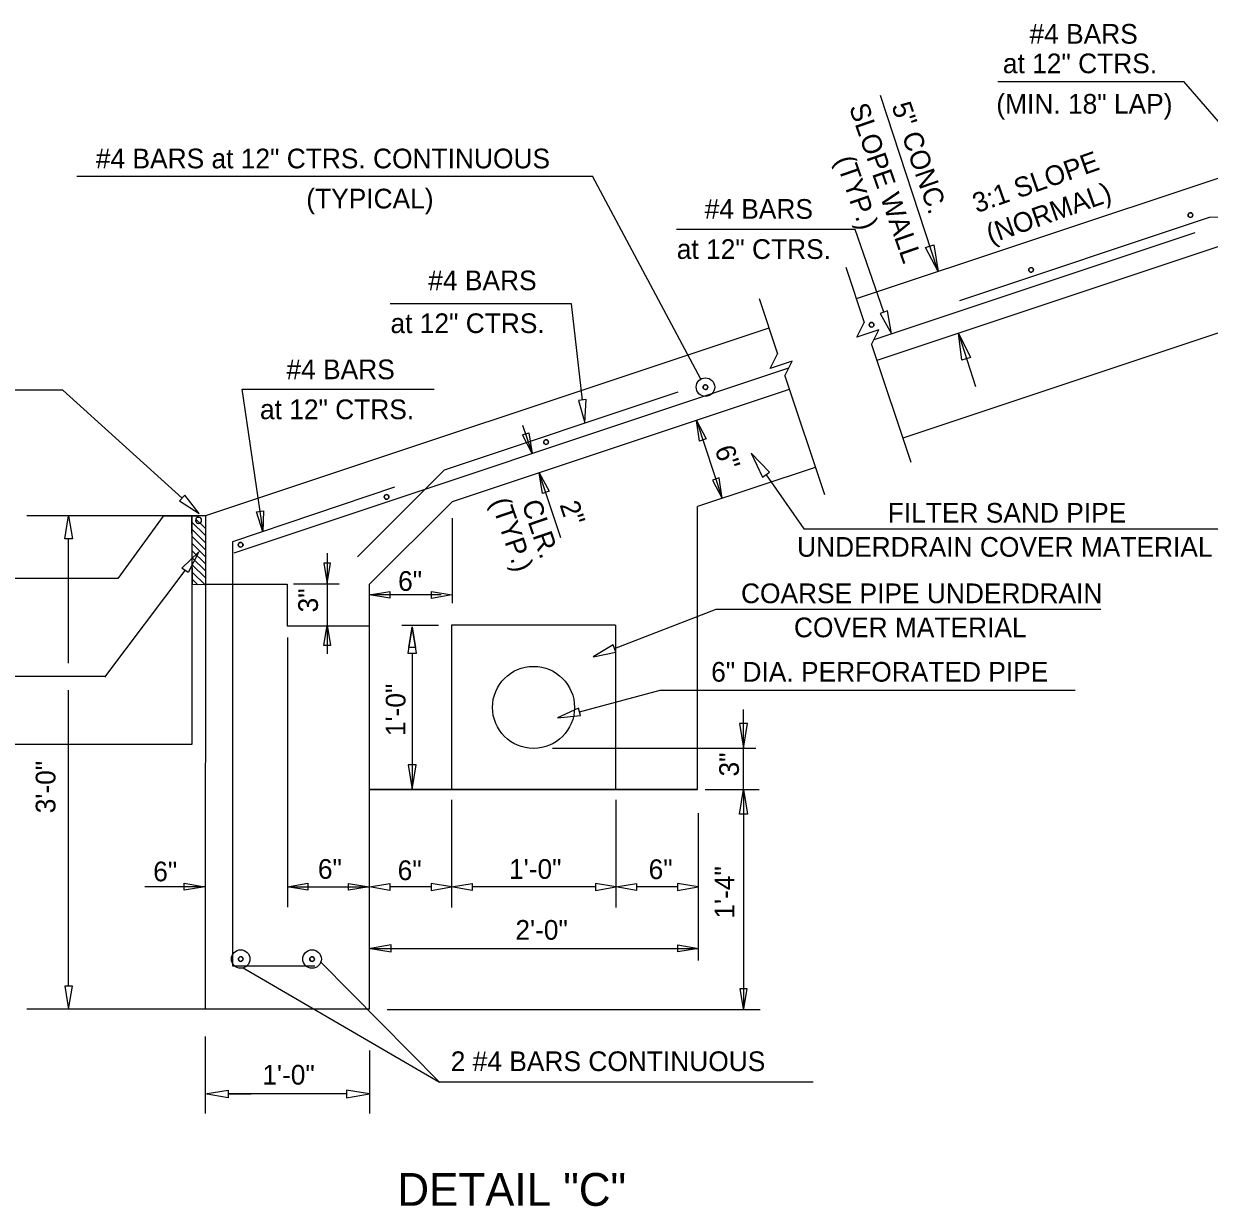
# Model space of a CAD drawing. Extents: x 570 to 2152770, y 726 to 139926.
# Drawn here: x 2152518.59 to 2152525.81, y 139385.58 to 139392.78 of the extents above; entities that cross this region are included whole.
import ezdxf

# ---------------------------------------------------------------- set-up
doc = ezdxf.new("R2010")
doc.units = 0
for name, color, linetype in [('4', 7, 'Continuous'), ('5', 7, 'Continuous'), ('6', 7, 'Continuous'), ('7', 7, 'Continuous'), ('9', 7, 'Continuous'), ('Default', 7, 'Continuous'), ('PR_Dimensions', 7, 'Continuous'), ('PR_Reinforcing', 7, 'Continuous'), ('PR_SlopeWall', 7, 'Continuous'), ('T', 7, 'Continuous'), ('T-Title', 7, 'Continuous'), ('TOPO_Concrete', 7, 'Continuous'), ('WEEPHOLES', 7, 'Continuous')]:
    doc.layers.add(name, color=color, linetype=linetype)

# ---------------------------------------------------------------- blocks, each defined once
blk = doc.blocks.new('DWG01008_7')
at = {"layer": 'Default'}
for p, q in [((-0.0132, 0), (0, 0.0132)), ((0, 0.0132), (0, -0.0132)), ((0, -0.0132), (0.0132, 0))]:
    blk.add_line(p, q, dxfattribs=at)
blk = doc.blocks.new('ARROWHD_15')
at = {"layer": 'Default'}
blk.add_lwpolyline([(0.0261, -0.0045), (0.0261, 0.0043), (-0.0004, -0.0001)], close=True, dxfattribs=at)

msp = doc.modelspace()

# ---------------------------------------------------------------- linework, layer by layer
at = {"layer": '4'}
for p, q in [((2152519.614, 139389.3656), (2152519.6114, 139389.7831)), ((2152519.6925, 139389.3691), (2152520.1925, 139389.3691)), ((2152520.1925, 139389.3691), (2152520.1925, 139389.1168)), ((2152520.1925, 139389.1168), (2152520.6925, 139389.1168))]:
    msp.add_line(p, q, dxfattribs=at)
at = {"layer": '5'}
for p, q in [((2152519.6917, 139389.7858), (2152519.6114, 139389.7831)), ((2152519.694, 139389.3684), (2152519.6137, 139389.3657))]:
    msp.add_line(p, q, dxfattribs=at)
at = {"layer": '6'}
msp.add_line((2152518.8249, 139390.5527), (2152515.2246, 139390.5527), dxfattribs=at)
at = {"layer": '7'}
for p, q in [((2152525.9667, 139390.9334), (2152523.9433, 139390.2589)), ((2152523.4102, 139390.0812), (2152522.693, 139389.8421)), ((2152522.693, 139388.1191), (2152522.693, 139389.8421)), ((2152522.693, 139388.1191), (2152520.693, 139388.1191))]:
    msp.add_line(p, q, dxfattribs=at)
at = {"layer": '9'}
for start, end in [(20.3306, 200.3306), (200.3306, 20.3306)]:
    msp.add_arc((2152523.7534, 139390.9506), 0.0143, start, end, dxfattribs=at)
at = {"layer": 'Default'}
for p, q in [((2152519.6919, 139389.6675), (2152519.6116, 139389.7468)), ((2152519.6916, 139389.7107), (2152519.6348, 139389.7668)), ((2152519.6922, 139389.6242), (2152519.6119, 139389.7035)), ((2152519.6924, 139389.5809), (2152519.6121, 139389.6602)), ((2152519.6927, 139389.5376), (2152519.6124, 139389.6169)), ((2152519.693, 139389.4943), (2152519.6127, 139389.5736)), ((2152519.6932, 139389.451), (2152519.6129, 139389.5303)), ((2152519.6935, 139389.4077), (2152519.6132, 139389.487)), ((2152519.6938, 139389.3645), (2152519.6135, 139389.4438)), ((2152519.6479, 139389.3667), (2152519.6137, 139389.4005))]:
    msp.add_line(p, q, dxfattribs=at)
at = {"layer": 'Defpoints'}
for p, q in [((2152519.6927, 139389.7858), (2152518.605, 139389.7858)), ((2152519.6927, 139386.7808), (2152518.605, 139386.7808))]:
    msp.add_line(p, q, dxfattribs=at)
at = {"layer": 'PR_Dimensions'}
for p, q in [((2152524.5223, 139392.4329), (2152525.6553, 139392.4329)), ((2152524.1583, 139391.2743), (2152523.8084, 139392.3468)), ((2152518.9105, 139391.8554), (2152522.0517, 139391.8554)), ((2152523.6523, 139391.5309), (2152522.5643, 139391.5309)), ((2152523.5961, 139391.3006), (2152523.7082, 139390.9643)), ((2152523.0673, 139391.1099), (2152523.1794, 139390.7736)), ((2152521.9237, 139391.0789), (2152520.8196, 139391.0789)), ((2152524.3895, 139390.5722), (2152524.286, 139390.8895)), ((2152523.7529, 139390.8302), (2152523.9916, 139390.1139)), ((2152523.2241, 139390.6395), (2152523.4655, 139389.9152)), ((2152520.0446, 139389.6891), (2152519.9167, 139390.5572)), ((2152519.9167, 139390.5572), (2152521.0867, 139390.5572)), ((2152521.6777, 139390.1885), (2152521.6282, 139390.3365)), ((2152522.6853, 139390.3666), (2152522.8436, 139389.8915)), ((2152521.8599, 139389.652), (2152521.7277, 139390.0474)), ((2152519.653, 139389.7858), (2152518.7392, 139389.7858)), ((2152521.1969, 139389.7722), (2152521.1969, 139389.2532)), ((2152518.8592, 139388.8881), (2152518.8592, 139389.6458)), ((2152520.4354, 139389.5592), (2152520.4354, 139389.1207)), ((2152520.5086, 139389.3697), (2152520.2294, 139389.3697)), ((2152521.1312, 139389.3044), (2152520.696, 139389.3044)), ((2152522.8053, 139389.2168), (2152525.1502, 139389.2168)), ((2152520.4354, 139389.1207), (2152520.4354, 139388.9459)), ((2152520.8895, 139389.1207), (2152521.1142, 139389.1207)), ((2152520.193, 139389.0439), (2152520.193, 139387.401)), ((2152516.2177, 139388.8086), (2152519.0795, 139388.8086)), ((2152518.8592, 139386.9208), (2152518.8592, 139388.7234)), ((2152522.4641, 139388.7248), (2152524.993, 139388.7248)), ((2152522.9726, 139388.1191), (2152522.9726, 139388.6058)), ((2152521.8092, 139388.3695), (2152523.0485, 139388.3695)), ((2152520.693, 139388.1191), (2152522.693, 139388.1191)), ((2152522.7399, 139388.1191), (2152523.0677, 139388.1191)), ((2152522.7432, 139388.1191), (2152523.0212, 139388.1191)), ((2152522.9726, 139388.1191), (2152522.9726, 139386.7812)), ((2152521.1938, 139388.0565), (2152521.1938, 139387.3998)), ((2152522.1954, 139388.0565), (2152522.1954, 139387.3998)), ((2152522.6962, 139387.9747), (2152522.6962, 139387.0758)), ((2152519.6931, 139387.526), (2152519.3246, 139387.526)), ((2152520.193, 139387.526), (2152520.693, 139387.526)), ((2152521.0686, 139387.525), (2152520.8182, 139387.525)), ((2152522.0702, 139387.525), (2152521.319, 139387.525)), ((2152522.571, 139387.525), (2152522.3206, 139387.525)), ((2152520.693, 139387.1508), (2152522.6962, 139387.1508)), ((2152519.9231, 139387.031), (2152521.1191, 139386.3345)), ((2152519.5727, 139386.7808), (2152518.7392, 139386.7808)), ((2152523.075, 139386.7753), (2152520.8007, 139386.7753)), ((2152519.6927, 139386.6144), (2152519.6927, 139386.1439)), ((2152520.6927, 139386.5286), (2152520.6927, 139386.1439)), ((2152523.3968, 139386.3345), (2152521.1191, 139386.3345)), ((2152519.8327, 139386.2639), (2152519.9727, 139386.2639)), ((2152520.5527, 139386.2639), (2152519.8327, 139386.2639))]:
    msp.add_line(p, q, dxfattribs=at)
for points in [[(2152526.2629, 139391.7323), (2152525.6553, 139392.4329)], [(2152522.712, 139390.6192), (2152522.0517, 139391.8554)], [(2152523.8277, 139391.0267), (2152523.6523, 139391.5309)], [(2152521.9907, 139390.4916), (2152521.9237, 139391.0789)], [(2152519.5519, 139389.8948), (2152518.8249, 139390.5527)], [(2152523.1102, 139390.0366), (2152523.3407, 139389.7073), (2152525.9183, 139389.7073)], [(2152519.5688, 139389.4541), (2152519.0787, 139388.8037)], [(2152522.187, 139388.9778), (2152522.8053, 139389.2168)], [(2152520.9533, 139388.9495), (2152520.9533, 139388.1191)], [(2152521.9738, 139388.5926), (2152522.4641, 139388.7248)], [(2152520.3969, 139387.0669), (2152521.1191, 139386.3345)]]:
    msp.add_lwpolyline(points, dxfattribs=at)
for points in [[(2152523.8057, 139391.0191), (2152523.8737, 139390.8945), (2152523.8498, 139391.0344)], [(2152521.9675, 139390.489), (2152522.0066, 139390.3525), (2152522.0139, 139390.4943)], [(2152522.7447, 139390.2544), (2152522.7051, 139390.2412), (2152522.6853, 139390.3666)], [(2152523.1321, 139390.0519), (2152523.0185, 139390.1676), (2152523.0884, 139390.0213)], [(2152522.8238, 139390.0169), (2152522.7843, 139390.0037), (2152522.8436, 139389.8915)], [(2152519.5362, 139389.8775), (2152519.6557, 139389.8009), (2152519.5675, 139389.9121)], [(2152518.8826, 139389.6458), (2152518.8359, 139389.6458), (2152518.8592, 139389.7858)], [(2152519.5501, 139389.4681), (2152519.653, 139389.5659), (2152519.5874, 139389.44)], [(2152520.4563, 139389.4986), (2152520.4146, 139389.4986), (2152520.4354, 139389.3736)], [(2152520.4563, 139388.9957), (2152520.4146, 139388.9957), (2152520.4354, 139389.1207)], [(2152520.98, 139388.9495), (2152520.9533, 139389.1095), (2152520.9267, 139388.9495)], [(2152520.9742, 139388.9843), (2152520.9325, 139388.9843), (2152520.9533, 139389.1095)], [(2152522.1786, 139388.9996), (2152522.0565, 139388.9273), (2152522.1954, 139388.956)], [(2152521.9677, 139388.6151), (2152521.8386, 139388.5561), (2152521.9799, 139388.57)], [(2152522.9977, 139388.5198), (2152522.9476, 139388.5198), (2152522.9726, 139388.3695)], [(2152520.9784, 139388.2694), (2152520.9283, 139388.2694), (2152520.9533, 139388.1191)], [(2152522.9977, 139387.9689), (2152522.9476, 139387.9689), (2152522.9726, 139388.1191)], [(2152520.8182, 139387.5459), (2152520.8182, 139387.5042), (2152520.693, 139387.525)], [(2152521.0686, 139387.5459), (2152521.0686, 139387.5042), (2152521.1938, 139387.525)], [(2152521.319, 139387.5459), (2152521.319, 139387.5042), (2152521.1938, 139387.525)], [(2152522.0702, 139387.5459), (2152522.0702, 139387.5042), (2152522.1954, 139387.525)], [(2152522.3206, 139387.5459), (2152522.3206, 139387.5042), (2152522.1954, 139387.525)], [(2152522.571, 139387.5459), (2152522.571, 139387.5042), (2152522.6962, 139387.525)], [(2152518.8826, 139386.9208), (2152518.8359, 139386.9208), (2152518.8592, 139386.7808)], [(2152522.9518, 139386.9062), (2152522.9935, 139386.9062), (2152522.9726, 139386.7812)], [(2152519.8327, 139386.2873), (2152519.8327, 139386.2406), (2152519.6927, 139386.2639)], [(2152520.5527, 139386.2873), (2152520.5527, 139386.2406), (2152520.6927, 139386.2639)]]:
    msp.add_lwpolyline(points, close=True, dxfattribs=at)
for centre in [(2152522.7406, 139390.5705), (2152519.9086, 139387.0855), (2152520.3435, 139387.0855)]:
    msp.add_circle(centre, 0.0565, dxfattribs=at)
for start, end in [(0.35771, 180.35771), (180.35771, 0.35771)]:
    msp.add_arc((2152519.6515, 139389.7581), 0.0188, start, end, dxfattribs=at)
at = {"layer": 'PR_Reinforcing'}
for p, q in [((2152528.7869, 139391.7267), (2152525.8113, 139391.6042)), ((2152525.8113, 139391.6042), (2152524.2887, 139391.0967)), ((2152525.7227, 139391.5108), (2152523.7673, 139390.8591)), ((2152523.2472, 139390.6857), (2152519.866, 139389.5586)), ((2152521.1515, 139390.0675), (2152522.5745, 139390.5418)), ((2152521.1515, 139390.0675), (2152520.6211, 139389.5372)), ((2152520.8458, 139389.9604), (2152519.8594, 139389.6274)), ((2152519.8594, 139389.6274), (2152519.8594, 139387.0441)), ((2152519.8594, 139387.0441), (2152520.3594, 139387.0441))]:
    msp.add_line(p, q, dxfattribs=at)
for centre in [(2152525.6963, 139391.6192), (2152524.725, 139391.2848), (2152523.753, 139390.9499), (2152522.7408, 139390.5705), (2152521.7696, 139390.2357), (2152520.7978, 139389.9016), (2152519.9083, 139389.6099), (2152519.9085, 139387.0858), (2152520.3435, 139387.0855)]:
    msp.add_circle(centre, 0.0143, dxfattribs=at)
for centre, start, end in [((2152525.6968, 139391.6192), 20.3306, 200.3306), ((2152525.6968, 139391.6192), 200.3306, 20.3306), ((2152524.7251, 139391.2849), 20.3306, 200.3306), ((2152524.7251, 139391.2849), 200.3306, 20.3306), ((2152522.7411, 139390.5701), 20.3306, 200.3306), ((2152522.7411, 139390.5701), 200.3306, 20.3306), ((2152521.7694, 139390.2358), 20.3306, 200.3306), ((2152521.7694, 139390.2358), 200.3306, 20.3306), ((2152520.7977, 139389.9015), 20.3306, 200.3306), ((2152520.7977, 139389.9015), 200.3306, 20.3306), ((2152519.9078, 139389.6098), 20.3306, 200.3306), ((2152519.9078, 139389.6098), 200.3306, 20.3306), ((2152519.9086, 139387.0855), 358.02811, 178.02811), ((2152519.9086, 139387.0855), 178.02811, 358.02811), ((2152520.3438, 139387.0855), 358.02811, 178.02811), ((2152520.3438, 139387.0855), 178.02811, 358.02811)]:
    msp.add_arc(centre, 0.0143, start, end, dxfattribs=at)
at = {"layer": 'PR_SlopeWall'}
for p, q in [((2152525.8755, 139391.8467), (2152523.6602, 139391.1083)), ((2152525.8755, 139391.43), (2152523.7852, 139390.7332)), ((2152525.8755, 139391.43), (2152523.7852, 139390.7332)), ((2152523.127, 139390.9306), (2152519.6934, 139389.786)), ((2152523.252, 139390.5555), (2152521.1969, 139389.8705)), ((2152521.1969, 139389.8705), (2152520.6933, 139389.3693)), ((2152519.6934, 139389.786), (2152519.6927, 139386.7788)), ((2152520.6927, 139386.7808), (2152520.6933, 139389.3693)), ((2152520.6927, 139386.7808), (2152519.6927, 139386.7808))]:
    msp.add_line(p, q, dxfattribs=at)
at = {"layer": 'T'}
msp.add_circle((2152521.693, 139388.6191), 0.25, dxfattribs=at)
at = {"layer": 'TOPO_Concrete'}
for p, q in [((2152519.6105, 139389.783), (2152519.6098, 139388.3924)), ((2152519.6098, 139388.3924), (2152517.9781, 139388.3924))]:
    msp.add_line(p, q, dxfattribs=at)
msp.add_lwpolyline([(2152519.6086, 139389.7832), (2152519.4352, 139389.7832), (2152519.1588, 139389.4038), (2152518.0424, 139389.4038)], dxfattribs=at)
at = {"layer": 'WEEPHOLES'}
for p, q in [((2152522.193, 139389.1191), (2152521.193, 139389.1191)), ((2152521.193, 139389.1191), (2152521.193, 139388.1191)), ((2152522.193, 139389.1191), (2152522.193, 139388.1191)), ((2152522.193, 139388.1191), (2152521.193, 139388.1191))]:
    msp.add_line(p, q, dxfattribs=at)

# ---------------------------------------------------------------- block references
at = {"layer": 'PR_Dimensions'}
for name, p, xscale, yscale, rotation in [('ARROWHD_15', (2152524.1579, 139391.2768), 6.151530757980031, -6.151530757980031, 108.14773664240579), ('DWG01008_7', (2152523.7305, 139390.8973), 5.344315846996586, -5.344315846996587, 108.43481291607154), ('ARROWHD_15', (2152524.2836, 139390.8968), 6.151530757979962, -6.151530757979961, -73.4582052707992), ('DWG01008_7', (2152523.2017, 139390.7065), 5.344315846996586, -5.344315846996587, 108.43481291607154), ('ARROWHD_15', (2152521.6849, 139390.1689), 4.724399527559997, -4.724399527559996, 108.7473059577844), ('ARROWHD_15', (2152521.728, 139390.0455), 4.724399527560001, -4.72439952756, -71.22552483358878), ('ARROWHD_15', (2152520.0446, 139389.691), 4.724399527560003, -4.724399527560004, 98.37998763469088), ('ARROWHD_15', (2152521.1937, 139389.3044), 4.7243995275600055, -4.7243995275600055, 180), ('ARROWHD_15', (2152519.6882, 139387.5266), 4.7243995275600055, -4.7243995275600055, 180), ('ARROWHD_15', (2152520.6897, 139387.526), 4.7243995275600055, -4.7243995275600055, 180), ('ARROWHD_15', (2152522.6963, 139387.1508), 4.731946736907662, -4.731946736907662, 180)]:
    msp.add_blockref(name, p, dxfattribs=dict(at, xscale=xscale, yscale=yscale, rotation=rotation))
for p, xscale, yscale in [((2152520.6949, 139389.3044), 4.7243995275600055, -4.7243995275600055), ((2152520.1949, 139387.5257), 4.7243995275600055, -4.7243995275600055), ((2152520.7012, 139387.1508), 4.731946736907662, 4.731946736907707)]:
    msp.add_blockref('ARROWHD_15', p, dxfattribs=dict(at, xscale=xscale, yscale=yscale))

# ---------------------------------------------------------------- texts
at = {"layer": 'T'}
for s, p in [('#4 BARS', (2152524.7155, 139392.6631)), ('at 12" CTRS.', (2152524.5535, 139392.4831)), ('(MIN. 18" LAP)', (2152524.5135, 139392.2369)), ('#4 BARS at 12" CTRS. CONTINUOUS', (2152519.026, 139391.9036)), ('(TYPICAL)', (2152520.3082, 139391.6593)), ('#4 BARS', (2152522.7362, 139391.5962)), ('at 12" CTRS.', (2152522.5661, 139391.3516)), ('#4 BARS', (2152521.0518, 139391.1608)), ('at 12" CTRS.', (2152520.8215, 139390.8997)), ('#4 BARS', (2152520.1874, 139390.6187)), ('at 12" CTRS.', (2152520.0259, 139390.3752)), ('FILTER SAND PIPE', (2152523.8519, 139389.7446)), ('UNDERDRAIN COVER MATERIAL', (2152523.299, 139389.5369)), ('6"', (2152520.8678, 139389.3291)), ('COARSE PIPE UNDERDRAIN', (2152522.9575, 139389.254)), ('COVER MATERIAL', (2152523.2802, 139389.0463)), ('6" DIA. PERFORATED PIPE', (2152522.7757, 139388.7757)), ('6"', (2152519.3754, 139387.5593)), ('6"', (2152520.3789, 139387.5745)), ('6"', (2152520.8652, 139387.5666)), ('1\'-0"', (2152521.5439, 139387.5742)), ('6"', (2152522.3945, 139387.5728)), ('2\'-0"', (2152521.5826, 139387.2033)), ('2 #4 BARS CONTINUOUS', (2152521.1886, 139386.4028)), ('1\'-0"', (2152520.0404, 139386.3204))]:
    msp.add_text(s, height=0.12, dxfattribs=at).set_placement(p)
for s, rotation, p in [('SLOPE WALL', 289.15235, (2152523.6146, 139392.2765)), ('5" CONC. ', 289.15235, (2152523.8734, 139392.284)), ('(TYP.)', 289.15235, (2152523.5312, 139391.9567)), ('3:1 SLOPE', 19.54423, (2152524.3944, 139391.6298)), ('(NORMAL)', 19.54423, (2152524.4784, 139391.4431)), ('6"', 288.92946, (2152522.7955, 139390.1929)), ('(TYP.)', 288.92946, (2152521.4312, 139389.8734)), ('CLR.', 288.92946, (2152521.6191, 139389.8615)), ('2"', 288.92946, (2152521.8504, 139389.8539)), ('3"', 90, (2152520.3793, 139389.1977)), ('1\'-0"', 90, (2152520.9127, 139388.4439)), ('3\'-0"', 90, (2152518.7793, 139387.9736)), ('3"', 90, (2152522.9448, 139388.1978)), ('1\'-4"', 90, (2152522.9171, 139387.3319))]:
    msp.add_text(s, height=0.12, rotation=rotation, dxfattribs=at).set_placement(p)
at = {"layer": 'T-Title'}
msp.add_text('DETAIL "C"', height=0.2, dxfattribs=at).set_placement((2152520.8635, 139385.5818))

doc.saveas('drawing.dxf')
